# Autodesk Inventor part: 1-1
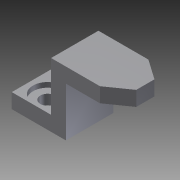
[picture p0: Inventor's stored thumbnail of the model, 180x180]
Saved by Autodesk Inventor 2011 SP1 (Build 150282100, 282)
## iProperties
Created: 2014-01
Part Number: 1-1
Document SubType Name: Modeling
Designer: Administrator
Density: 1 g/cm^3
Author: Administrator
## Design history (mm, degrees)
sketch "草图1"
  geometry: L1 (-8.165, 4.81)-(-8.165, -4.81); L2 (-8.165, 4.81)-(1.999, 4.81); L3 (-8.165, -4.81)-(1.762, -4.81); L4 (1.999, 4.81)-(6.095, 1.942); L5 (6.095, 1.942)-(6.095, -1.776); L6 (1.762, -4.81)-(6.095, -1.776); 2 further points
  constraints: 12 end point, 2 perpendicular, 1 horizontal alignment, 1 midpoint, 1 parallel, 1 vertical
  dimensions: "d0" = 5 distance of L2.end L4.end; "d1" = 145 deg angle of L4 L2; "d2" = 145 deg angle of L3 L6
extrude "拉伸1" new body sketch "草图1" distance "d3" = 3; taper "d4" = 0 deg
sketch "草图2"
  geometry: L1 (8.165, 4.81)-(8.165, -4.81) reference; L2 (-1.999, 4.81)-(8.165, 4.81) reference; L3 (8.165, -4.81)-(-1.762, -4.81) reference; L4 (8.165, 4.81)-(5.165, 4.81); L5 (5.165, 4.81)-(5.165, -4.81); L6 (5.165, -4.81)-(8.165, -4.81); 1 further point
  constraints: 6 end point, 2 point on line, 1 collinear, 1 perpendicular
  dimensions: "d5" = 3 distance of L1.start L4.end
extrude "拉伸2" join sketch "草图2" distance "d6" = 10; taper "d7" = 0 deg
sketch "草图3"
  geometry: L1 (8.165, 4.81)-(8.165, -4.81) reference; L2 (5.165, 4.81)-(8.165, 4.81) reference; L3 (5.165, -4.81)-(5.165, 4.81) reference; L4 (8.165, -4.81)-(16.165, -4.81); L5 (16.165, -4.81)-(16.165, 4.81); L6 (16.165, 4.81)-(8.165, 4.81); 1 further point
  constraints: 6 end point, 2 perpendicular, 1 collinear
  dimensions: "d8" = 8 distance of L1.end L4.end
extrude "拉伸3" join sketch "草图3" distance "d9" = 3; taper "d10" = 0 deg
sketch "草图4"
  geometry: L1 (-8, 10)-(0, 10) reference; L2 (0, 0)-(0, 10) reference; L3 (0, 2.021)-(-6.124, 10); L4 (0, 2.021)-(0, 10); L5 (0, 10)-(-6.124, 10); 1 further point
  constraints: 6 end point, 2 collinear, 2 point on line
extrude "拉伸4" join sketch "草图4" distance "d11" = 3; taper "d12" = 0 deg
sketch "草图5"
  geometry: C1 r 3 at (-12.165, -1.5); 1 further point
  constraints: 1 centre point
extrude "拉伸5" cut sketch "草图5" distance "d14" = 1; taper "d15" = 0 deg
hole "Hole1" diameter "d18" = 3; stored, may be unused: countersink angle "d22" = 90 deg, drill point angle "d24" = 0 deg; dims "d16" = 10, "d17" = 10, "d19" = 6, "d20" = 4, "d21" = 2, "d23" = 8
node "实体1"
